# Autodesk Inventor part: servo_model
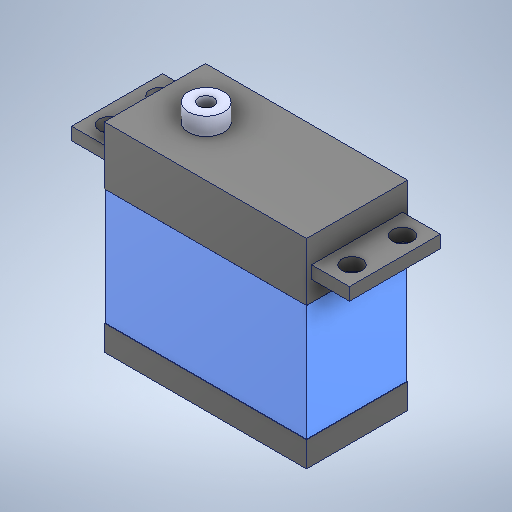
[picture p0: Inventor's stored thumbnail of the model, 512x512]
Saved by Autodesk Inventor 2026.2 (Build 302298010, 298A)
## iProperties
Created: 1705-05
Part Number: servo_model
Material: Générique
Document SubType Name: Modeling
Designer: mel
Density: 1 g/cm^3
Appearance: Par défaut
Author: mel
Sending System: SOLIDWORKS 2017
Last Saved Date: 2023-06-07
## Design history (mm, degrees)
feature "Symétrie2"
sketch "Esquisse1"
  geometry: C1 r 1.5 at (0, 0) reference; 1 further point
extrude "Extrusion1" cut sketch "Esquisse1" distance "d0" = 10; taper "d1" = 0 deg
node "Solide1"
